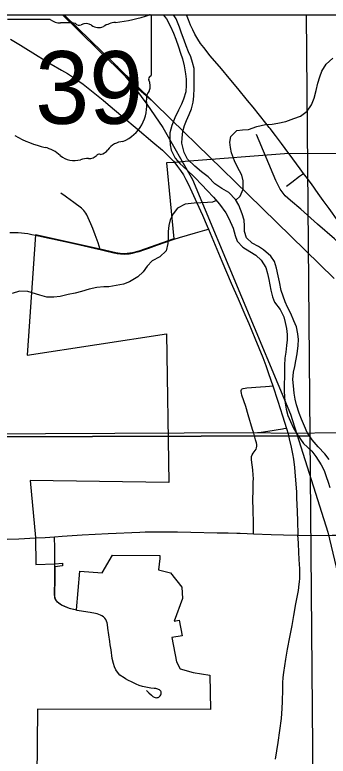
# Model space of a CAD drawing. Extents: x 0 to 34, y 0 to 22.
# Drawn here: x 2.561 to 3.129, y 16.14 to 17.485 of the extents above; entities that cross this region are included whole.
import ezdxf

# ---------------------------------------------------------------- set-up
doc = ezdxf.new("R2010")
doc.units = 0
for name, color, linetype in [('GM_X_County_Road', 7, 'Continuous'), ('GM_X_County_Road_Text', 7, 'Continuous'), ('GM_X_County_Text', 7, 'Continuous'), ('GM_X_Interchange_Ramps', 7, 'Continuous'), ('GM_X_State_Route', 7, 'Continuous'), ('GM_X_State_Shield', 7, 'Continuous'), ('GM_X_Township_Road', 7, 'Continuous'), ('SH_Text', 7, 'Continuous')]:
    doc.layers.add(name, color=color, linetype=linetype)

msp = doc.modelspace()

# ---------------------------------------------------------------- linework, layer by layer
at = {"layer": 'GM_X_County_Road'}
for p, q in [((2.8086, 17.3774), (2.8086, 17.4821)), ((2.6247, 17.4771), (2.5475, 17.4771)), ((2.8085, 17.3774), (2.8086, 17.3774))]:
    msp.add_line(p, q, dxfattribs=at)
for points in [[(2.5525, 17.4416), (2.5711, 17.4302), (2.6028, 17.4106), (2.6267, 17.3961), (2.6454, 17.3851), (2.656, 17.3787), (2.6692, 17.3703), (2.6769, 17.3651), (2.6845, 17.3597), (2.6968, 17.3502), (2.7089, 17.3404), (2.7209, 17.3305), (2.7303, 17.3225), (2.7564, 17.3005), (2.7826, 17.2785), (2.8112, 17.2546), (2.8286, 17.2397), (2.8434, 17.2256), (2.8483, 17.2201), (2.851, 17.2171)], [(2.851, 17.2171), (2.856, 17.2104), (2.8614, 17.2028), (2.8665, 17.1949), (2.8712, 17.1868), (2.8755, 17.1785), (2.8821, 17.1643), (2.8911, 17.1445), (2.9012, 17.1217), (2.9097, 17.1017), (2.9119, 17.0966), (2.9366, 17.0387), (2.9535, 16.9985), (2.9657, 16.9699), (2.9782, 16.9414), (2.9851, 16.925)], [(2.9851, 16.925), (2.9963, 16.8984), (3.0105, 16.8638), (3.016, 16.8493), (3.0211, 16.8345), (3.0286, 16.8122), (3.0379, 16.7844), (3.0465, 16.7577), (3.0538, 16.7345), (3.0565, 16.725), (3.0588, 16.7159), (3.0623, 16.7007), (3.0647, 16.6885), (3.0662, 16.6792), (3.0681, 16.6638), (3.0697, 16.6483), (3.0706, 16.6341), (3.0716, 16.6194), (3.0721, 16.6073)], [(3.0721, 16.6073), (3.0725, 16.5982), (3.0738, 16.5677), (3.0742, 16.5409)], [(3.0742, 16.5409), (3.0988, 16.5408), (3.1369, 16.5409), (3.1391, 16.5409), (3.1608, 16.5409), (3.2042, 16.541), (3.2197, 16.5409), (3.2413, 16.5404), (3.2447, 16.5403), (3.2723, 16.5394), (3.2873, 16.5391)]]:
    msp.add_lwpolyline(points, dxfattribs=at)
for centre, radius, start, end in [((2.7146, 17.75), 0.2796, 275.8445, 288.9065), ((2.8056, 17.4825), 0.00294, 351.8621, 97.738), ((2.6431, 17.5004), 0.0296, 231.6195, 271.1119), ((2.6529, 17.3648), 0.1064, 80.4867, 94.9883), ((2.6771, 17.4751), 0.00855, 219.7921, 297.1024), ((2.6896, 17.452), 0.0178, 54.4667, 119.1411), ((2.7125, 17.4837), 0.0214, 233.8562, 294.8282), ((2.7503, 17.416), 0.0563, 97.3462, 120.7689), ((2.8079, 17.3697), 0.00454, 107.944, 210.337), ((2.8054, 17.377), 0.00314, 289.6038, 7.7341), ((2.779, 17.3565), 0.0273, 340.033, 23.6496), ((2.8191, 17.3336), 0.0198, 136.8065, 186.9296), ((2.7303, 17.3203), 0.0699, 292.3089, 8.9858), ((2.6603, 17.4418), 0.2019, 240.4129, 257.1985), ((2.7598, 17.2174), 0.0383, 94.4031, 142.5768), ((2.6001, 17.1837), 0.0632, 47.1842, 75.836), ((2.7113, 17.2542), 0.0226, 282.8732, 323.2771), ((2.6684, 17.261), 0.0401, 230.7004, 286.2918), ((2.6916, 17.1918), 0.0329, 85.6951, 111.2099), ((2.6945, 17.246), 0.0214, 268.777, 315.5493), ((2.7138, 17.2267), 0.00601, 65.7517, 132.6484)]:
    msp.add_arc(centre, radius, start, end, dxfattribs=at)
at = {"layer": 'GM_X_County_Road_Text'}
for points in [[(2.9615, 17.1492), (2.9696, 17.1562), (2.9748, 17.1692), (2.9752, 17.1843), (2.9725, 17.1942), (2.9644, 17.2101), (2.9595, 17.2203), (2.9541, 17.2351), (2.9518, 17.2446), (2.951, 17.2541), (2.9528, 17.2647), (2.9638, 17.2758), (2.974, 17.2766), (2.985, 17.2774), (3.0001, 17.2827), (3.0157, 17.2862), (3.0278, 17.287), (3.038, 17.2886), (3.0524, 17.292), (3.0671, 17.2974), (3.0789, 17.3016), (3.091, 17.3104), (3.0992, 17.3222), (3.1037, 17.334), (3.1075, 17.3484), (3.1108, 17.3617), (3.1142, 17.3727), (3.1176, 17.3834), (3.1258, 17.3959), (3.1379, 17.4066)], [(2.9266, 17.1483), (2.9196, 17.1454), (2.9101, 17.145), (2.898, 17.1442), (2.8863, 17.1434), (2.8696, 17.1418), (2.856, 17.1346), (2.8477, 17.1243), (2.8424, 17.1136), (2.8402, 17.1034), (2.8391, 17.092), (2.8388, 17.0825), (2.8381, 17.0707), (2.8355, 17.0574), (2.8238, 17.046), (2.8098, 17.0391), (2.8011, 17.0296), (2.7936, 17.0193), (2.7838, 17.0102), (2.7686, 17.001), (2.7577, 16.9968), (2.7444, 16.9941), (2.7315, 16.9918), (2.7221, 16.9917), (2.7092, 16.9906), (2.6956, 16.9875), (2.6815, 16.9832), (2.6702, 16.9805), (2.6573, 16.9778), (2.6429, 16.9744), (2.6316, 16.9728), (2.6187, 16.9731), (2.6062, 16.9769), (2.584, 16.9834)], [(2.584, 16.9834), (2.5688, 16.9838), (2.5559, 16.98)]]:
    msp.add_lwpolyline(points, dxfattribs=at)
at = {"layer": 'GM_X_County_Text'}
for points in [[(2.6469, 17.4855), (2.6735, 17.4594), (2.7174, 17.4165), (2.7446, 17.3902), (2.7806, 17.3549), (2.8082, 17.3312)], [(2.6502, 17.4855), (2.6752, 17.4611), (2.719, 17.4182), (2.7463, 17.3919), (2.8446, 17.2955), (2.9838, 17.1603), (3.1405, 17.007)], [(2.746, 17.3924), (2.7798, 17.3511), (2.8003, 17.3234), (2.829, 17.2812), (2.8831, 17.1865), (3.0608, 16.761), (3.1285, 16.5463), (3.171, 16.3684), (3.2444, 16.0416)], [(3.3183, 16.8326), (3.2885, 16.868), (3.2742, 16.8866), (3.2602, 16.9097), (3.165, 17.0547), (3.1409, 17.0789), (3.1097, 17.1053), (3.0797, 17.1328), (3.0609, 17.1485), (3.0515, 17.1567), (3.0425, 17.1689), (3.0345, 17.185), (2.9995, 17.2681)]]:
    msp.add_lwpolyline(points, dxfattribs=at)
at = {"layer": 'GM_X_Interchange_Ramps'}
msp.add_line((2.6334, 16.4833), (2.6334, 16.4886), dxfattribs=at)
for points in [[(2.7155, 17.0594), (2.7135, 17.0654), (2.7116, 17.0714), (2.7066, 17.086), (2.7023, 17.0975), (2.6988, 17.106), (2.6937, 17.1172), (2.691, 17.1227), (2.6894, 17.1254), (2.6877, 17.128), (2.6858, 17.1304), (2.6837, 17.1326), (2.6814, 17.1346), (2.6674, 17.145), (2.6542, 17.1548), (2.6493, 17.1584), (2.6467, 17.1601), (2.644, 17.1616)], [(2.5514, 17.0907), (2.5669, 17.0902), (2.5725, 17.0899), (2.5782, 17.0893), (2.5842, 17.0886), (2.5913, 17.0871), (2.5982, 17.0857)], [(2.8496, 17.0781), (2.8596, 17.0811), (2.8741, 17.0856), (2.8887, 17.0898), (2.9056, 17.0947), (2.9119, 17.0966)], [(2.5982, 17.0857), (2.62, 17.081), (2.629, 17.0792), (2.6652, 17.0712), (2.6863, 17.0664), (2.7073, 17.0614), (2.7155, 17.0594)], [(2.7155, 17.0594), (2.7253, 17.057), (2.7403, 17.0536), (2.744, 17.053), (2.7464, 17.0525), (2.7526, 17.0517), (2.7557, 17.0515), (2.7588, 17.0514), (2.7619, 17.0515), (2.765, 17.0517), (2.768, 17.052), (2.7711, 17.0525), (2.7741, 17.053), (2.7801, 17.0545), (2.7861, 17.0562), (2.7949, 17.0589), (2.8037, 17.0619), (2.8181, 17.0674), (2.8496, 17.0781)], [(2.6334, 16.4886), (2.6333, 16.497), (2.633, 16.5176), (2.6325, 16.538)], [(2.6736, 16.4046), (2.6726, 16.4048), (2.6596, 16.4083), (2.6538, 16.4103), (2.6509, 16.4115), (2.6454, 16.4143), (2.6428, 16.4158), (2.6403, 16.4176), (2.638, 16.4196), (2.636, 16.4218), (2.6344, 16.4243), (2.6335, 16.427), (2.633, 16.4299), (2.6328, 16.433), (2.6328, 16.4391), (2.6331, 16.4557), (2.6334, 16.4833)], [(2.7993, 16.2591), (2.804, 16.2551), (2.8085, 16.2507), (2.8109, 16.2486), (2.8138, 16.2469), (2.8155, 16.2463), (2.8171, 16.2461), (2.8188, 16.2462), (2.8205, 16.2467), (2.8221, 16.2474), (2.8234, 16.2485), (2.8246, 16.2496), (2.8256, 16.2511), (2.8262, 16.2528), (2.8264, 16.2546), (2.826, 16.2565), (2.8254, 16.258), (2.8242, 16.2594), (2.8229, 16.2604), (2.8215, 16.2612), (2.8199, 16.2619), (2.8167, 16.2626), (2.8136, 16.263), (2.8073, 16.2636), (2.8012, 16.2644), (2.7982, 16.265), (2.7923, 16.2666), (2.7865, 16.2685), (2.7808, 16.2709), (2.7723, 16.2747), (2.7668, 16.2774), (2.7614, 16.2804), (2.7588, 16.282), (2.7512, 16.2872), (2.7469, 16.2922), (2.7438, 16.2969), (2.7416, 16.3023), (2.7395, 16.3083), (2.7375, 16.3171), (2.7353, 16.3328), (2.7338, 16.3418), (2.7329, 16.3479), (2.7311, 16.3602), (2.7296, 16.3725), (2.7286, 16.3787), (2.728, 16.3818), (2.727, 16.3849), (2.7256, 16.3879), (2.7237, 16.3905), (2.7214, 16.3928), (2.7188, 16.3947), (2.7159, 16.3962), (2.7129, 16.3973), (2.7099, 16.3981), (2.7068, 16.3989), (2.6976, 16.4006), (2.6852, 16.4024), (2.6736, 16.4046)]]:
    msp.add_lwpolyline(points, dxfattribs=at)
at = {"layer": 'GM_X_State_Route'}
for points in [[(3.0896, 17.4855), (3.0962, 16.7214), (2.1086, 16.7183), (2.1019, 17.4855)], [(3.6061, 17.2319), (3.0581, 17.2338), (2.8696, 17.2191), (2.8508, 17.2176), (2.8361, 17.2166), (2.8494, 17.0787), (2.7859, 17.0567), (2.7739, 17.0536), (2.7647, 17.0522), (2.7555, 17.052), (2.7438, 17.0535), (2.7152, 17.0599), (2.598, 17.0862), (2.5827, 16.868), (2.8356, 16.9066), (2.8402, 16.6365), (2.5882, 16.6405), (2.5982, 16.5366), (2.5989, 16.4878), (2.6332, 16.4891), (2.6469, 16.4903), (2.647, 16.4853), (2.6332, 16.4838), (2.6329, 16.4563), (2.6326, 16.4397), (2.6326, 16.4335), (2.6328, 16.4305), (2.6333, 16.4275), (2.6342, 16.4248), (2.6358, 16.4223), (2.6378, 16.4201), (2.6401, 16.4181), (2.6426, 16.4164), (2.6452, 16.4148), (2.6507, 16.412), (2.6536, 16.4108), (2.6594, 16.4089), (2.6724, 16.4053), (2.6787, 16.4755), (2.7189, 16.4727), (2.7378, 16.5051), (2.8235, 16.5041), (2.8239, 16.4988), (2.8214, 16.4781), (2.8433, 16.4726), (2.8637, 16.4465), (2.8647, 16.4261), (2.8497, 16.3848), (2.859, 16.3866), (2.8644, 16.3587), (2.8458, 16.3551), (2.8543, 16.3114), (2.8605, 16.2986), (2.8842, 16.2918), (2.9148, 16.287), (2.9156, 16.2249), (2.6016, 16.2256), (2.5958, 15.6001)], [(3.0536, 17.1747), (3.0635, 17.1819), (3.0776, 17.1927), (3.0845, 17.1978)], [(3.0538, 16.7345), (3.0491, 16.7339), (3.0464, 16.7335), (3.0197, 16.7293), (3.0078, 16.7277), (2.9942, 16.7261), (2.9921, 16.7327), (2.984, 16.7597), (2.9796, 16.7747), (2.9727, 16.7955), (2.972, 16.7986), (2.9712, 16.8018), (2.9714, 16.8037), (2.9722, 16.8054), (2.9735, 16.8065), (2.9752, 16.8073), (2.9785, 16.808), (2.9815, 16.8083), (3.0064, 16.8102), (3.0157, 16.811), (3.0231, 16.8117), (3.0286, 16.8122)], [(4.1201, 16.507), (4.1149, 16.7255), (3.8667, 16.7261), (3.8624, 16.726), (3.8538, 16.7259), (3.7775, 16.7251), (3.6944, 16.7259), (3.6091, 16.7254), (3.5492, 16.7252), (3.5064, 16.7242), (3.4642, 16.7247), (3.3781, 16.7258), (3.3363, 16.7271), (3.2929, 16.7282), (3.2508, 16.7281), (3.0563, 16.7255), (2.994, 16.7266), (1.8602, 16.7212), (1.8602, 14.3866), (4.1451, 14.3866)], [(2.9936, 16.6442), (2.9935, 16.6503), (2.9927, 16.6594), (2.9915, 16.6685), (2.9901, 16.6777), (2.9899, 16.6808), (2.9902, 16.6841), (2.9913, 16.6871), (2.9931, 16.6898), (2.9971, 16.6945), (2.9986, 16.697), (2.9994, 16.6996), (2.9998, 16.7025), (2.9997, 16.7054), (2.9992, 16.7084), (2.9976, 16.7142), (2.9942, 16.7261)], [(2.9941, 16.5437), (2.9939, 16.5523), (2.9937, 16.5635), (2.9931, 16.5863), (2.9929, 16.6064), (2.993, 16.6218), (2.9933, 16.6372), (2.9936, 16.6442)], [(3.0339, 16.1343), (3.0386, 16.165), (3.0417, 16.1866), (3.0445, 16.2082), (3.0454, 16.2175), (3.0461, 16.2268), (3.0467, 16.2392), (3.0469, 16.261), (3.0473, 16.2734), (3.0479, 16.2826), (3.0487, 16.2918), (3.0504, 16.3041), (3.0524, 16.3163), (3.0557, 16.3345), (3.0598, 16.3558), (3.0638, 16.377), (3.0671, 16.3953), (3.0709, 16.4165), (3.0726, 16.4256), (3.0752, 16.4409), (3.077, 16.452), (3.0775, 16.4563), (3.0778, 16.4626), (3.0778, 16.4689), (3.0778, 16.4813), (3.0776, 16.4875), (3.0761, 16.5091), (3.0752, 16.5269), (3.0742, 16.5409)]]:
    msp.add_lwpolyline(points, dxfattribs=at)
msp.add_lwpolyline([(2.1086, 16.7183), (3.0962, 16.7214), (3.1048, 15.7312), (2.0927, 15.7254)], close=True, dxfattribs=at)
at = {"layer": 'GM_X_State_Shield'}
for points in [[(2.8298, 17.4855), (2.8356, 17.4783), (2.8432, 17.4643), (2.8486, 17.4525), (2.8528, 17.4416), (2.8574, 17.4275), (2.8612, 17.4158), (2.8651, 17.4056), (2.8678, 17.3927), (2.8705, 17.3786), (2.8713, 17.3688), (2.8717, 17.3581), (2.871, 17.3456), (2.8669, 17.3327), (2.8631, 17.3232), (2.8575, 17.3122), (2.8511, 17.2985), (2.8455, 17.2848), (2.8421, 17.2711), (2.8418, 17.2597), (2.8426, 17.2495), (2.8446, 17.24), (2.8514, 17.2252), (2.8602, 17.2154), (2.8727, 17.2041), (2.8872, 17.1901), (2.8998, 17.1768), (2.9097, 17.1666), (2.9211, 17.1545), (2.9321, 17.1421), (2.9436, 17.1262), (2.9493, 17.1156), (2.9566, 17.0981), (2.9608, 17.0849), (2.9642, 17.075), (2.9745, 17.064), (2.9871, 17.0557), (2.9981, 17.0493), (3.008, 17.0403), (3.0164, 17.027), (3.0194, 17.016), (3.0218, 17.005), (3.0237, 16.9952), (3.0253, 16.9857), (3.028, 16.9739), (3.0322, 16.9637), (3.0421, 16.9505), (3.0486, 16.9372), (3.0513, 16.9273), (3.0536, 16.9163), (3.0552, 16.9053), (3.0548, 16.8959), (3.0537, 16.8856), (3.0523, 16.8735), (3.0508, 16.8625), (3.0501, 16.8488), (3.0498, 16.8393), (3.0498, 16.8264), (3.0495, 16.8169), (3.0495, 16.8036), (3.0503, 16.7907), (3.0511, 16.7809), (3.0531, 16.7695), (3.0562, 16.7585), (3.0608, 16.7475), (3.0665, 16.7354), (3.0734, 16.7233), (3.0848, 16.7074), (3.0996, 16.6938), (3.1069, 16.6839), (3.1168, 16.6688), (3.1218, 16.6586)], [(3.0912, 16.7275), (3.0862, 16.7389), (3.0812, 16.7514), (3.077, 16.7627), (3.072, 16.7779), (3.0697, 16.7878), (3.0674, 16.7991), (3.0662, 16.8124), (3.0654, 16.8238), (3.0664, 16.8367), (3.0687, 16.847), (3.0705, 16.8576), (3.0731, 16.8705), (3.075, 16.8853), (3.0753, 16.8963), (3.0741, 16.9066), (3.0718, 16.9191), (3.0668, 16.9301), (3.0618, 16.9433), (3.0557, 16.9547), (3.0515, 16.9645), (3.0477, 16.9748), (3.0442, 16.9854), (3.0411, 17.0009), (3.0384, 17.0119), (3.0357, 17.0256), (3.0322, 17.0377), (3.0254, 17.0475), (3.0121, 17.0589), (3.0026, 17.0653), (2.9912, 17.0709), (2.9809, 17.0808), (2.9774, 17.0921), (2.9774, 17.1024), (2.9766, 17.113), (2.9735, 17.1244), (2.967, 17.1403), (2.9609, 17.1501), (2.9491, 17.163), (2.9366, 17.1705), (2.9236, 17.1788), (2.9115, 17.1913), (2.8993, 17.2008), (2.8871, 17.2106), (2.8742, 17.2234), (2.8677, 17.2355), (2.8638, 17.2526), (2.8642, 17.2625), (2.8656, 17.2735), (2.8686, 17.2845), (2.8724, 17.294), (2.8769, 17.3043), (2.8814, 17.3149), (2.884, 17.3271), (2.8854, 17.3381), (2.8861, 17.3521), (2.8861, 17.3639), (2.8864, 17.3757), (2.886, 17.3878), (2.8833, 17.3992), (2.8798, 17.409), (2.876, 17.4185), (2.8718, 17.4295), (2.868, 17.4393), (2.8634, 17.4522), (2.8595, 17.4628), (2.8534, 17.4784), (2.8488, 17.4855)], [(3.1312, 16.6787), (3.1232, 16.6885), (3.111, 16.7014), (3.1003, 16.7143), (3.0912, 16.7275)], [(3.1218, 16.6586), (3.126, 16.6476), (3.1291, 16.6373), (3.1321, 16.6275)]]:
    msp.add_lwpolyline(points, dxfattribs=at)
at = {"layer": 'GM_X_Township_Road'}
for points in [[(3.0222, 17.2812), (3.0162, 17.2887), (3.0046, 17.3033), (2.993, 17.3179), (2.9832, 17.33), (2.9655, 17.3517), (2.9496, 17.3708), (2.9355, 17.3874), (2.9154, 17.4111), (2.9036, 17.4259), (2.8979, 17.4335), (2.8928, 17.4414), (2.8873, 17.4505), (2.8835, 17.4582), (2.8795, 17.4667), (2.8756, 17.4763), (2.8719, 17.4855)], [(3.0577, 17.234), (3.0445, 17.2518), (3.0335, 17.2667), (3.0239, 17.2789), (3.0222, 17.2812)], [(3.0845, 17.1978), (3.0783, 17.206), (3.0583, 17.2332), (3.0577, 17.234)], [(3.2264, 17.0033), (3.2189, 17.0134), (3.2116, 17.0235), (3.2027, 17.0362), (3.1955, 17.0462), (3.1809, 17.0662), (3.168, 17.0837), (3.1477, 17.1112), (3.1313, 17.1337), (3.1204, 17.1484), (3.1114, 17.161), (3.0989, 17.1788), (3.0896, 17.1912), (3.0845, 17.1978)], [(2.1045, 16.5107), (2.1433, 16.5122), (2.1651, 16.5128), (2.1838, 16.5134), (2.1993, 16.514), (2.2303, 16.5153), (2.2552, 16.5166), (2.2676, 16.5171), (2.2924, 16.5186), (2.3079, 16.5195), (2.3172, 16.52), (2.3265, 16.5207), (2.342, 16.5216), (2.3575, 16.5226), (2.3792, 16.524), (2.3947, 16.525), (2.4258, 16.5267), (2.4629, 16.5288), (2.5094, 16.5316), (2.5341, 16.533), (2.5465, 16.5337), (2.5681, 16.5346), (2.5984, 16.536)], [(2.5984, 16.536), (2.6157, 16.5371), (2.6325, 16.538)], [(2.6325, 16.538), (2.6468, 16.5392), (2.683, 16.5418), (2.7299, 16.5442), (2.7876, 16.5467), (2.7969, 16.5471), (2.8093, 16.5473), (2.8186, 16.5473), (2.8556, 16.5473), (2.8801, 16.5467), (2.9278, 16.5456), (2.948, 16.5451), (2.9635, 16.5448), (2.9697, 16.5446), (2.9822, 16.5441), (2.9941, 16.5437)], [(2.9941, 16.5437), (3.0256, 16.5425), (3.0485, 16.5419), (3.0742, 16.5409)]]:
    msp.add_lwpolyline(points, dxfattribs=at)
at = {"layer": 'SH_Text'}
msp.add_line((2.0719, 17.4855), (4.0477, 17.4855), dxfattribs=at)

# ---------------------------------------------------------------- texts
at = {"layer": 'GM_X_County_Road'}
msp.add_text('39', height=0.13184, dxfattribs=at).set_placement((2.5975, 17.2877))

doc.saveas('drawing.dxf')
